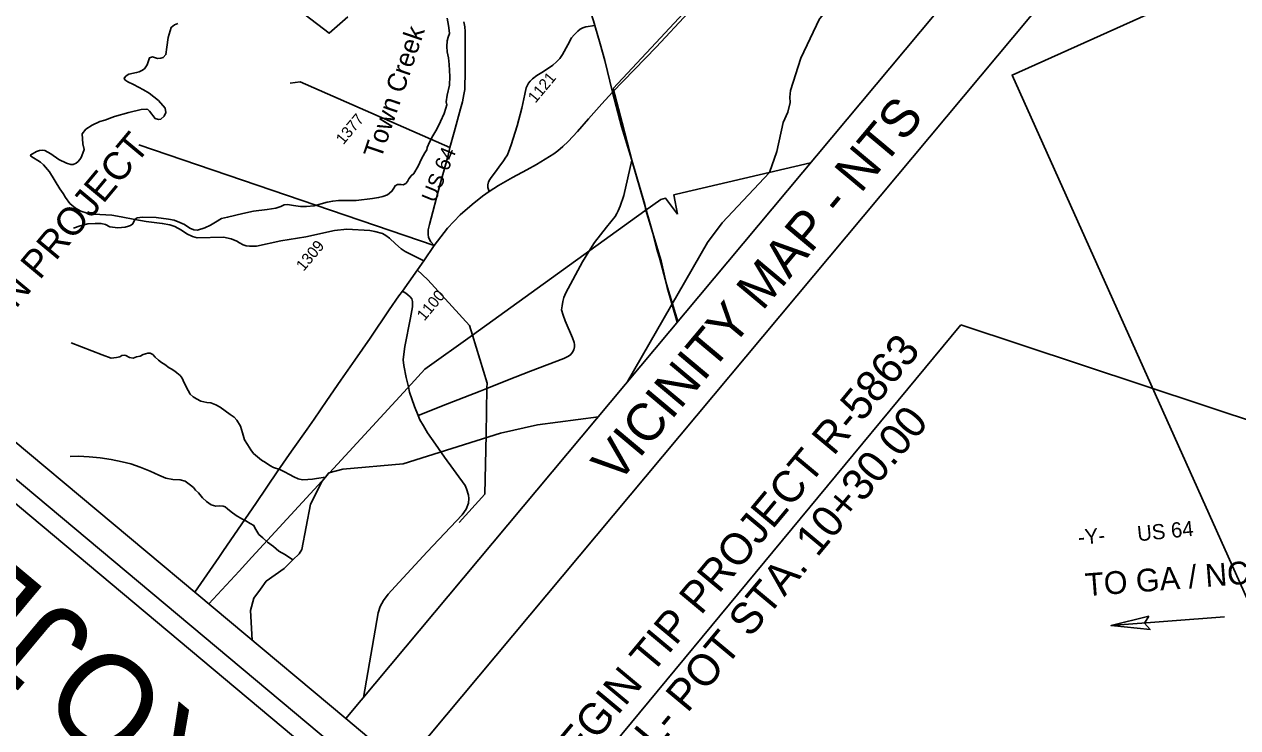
# Model space of a CAD drawing. Extents: x 555292 to 2368606, y 503623 to 1171444.
# Drawn here: x 2356645 to 2358242, y 1162339 to 1163265 of the extents above; entities that cross this region are included whole.
import ezdxf

# ---------------------------------------------------------------- set-up
doc = ezdxf.new("R2010")
doc.units = 0
for name, color, linetype in [('Exist Road Non-System Type 51 Label', 7, 'Continuous'), ('Exist Roads EOP Text', 7, 'Continuous'), ('Old_Level_1', 7, 'Continuous'), ('Old_Level_22', 7, 'Continuous'), ('Old_Level_28', 7, 'Continuous'), ('Old_Level_29', 7, 'Continuous'), ('Old_Level_3', 7, 'Continuous'), ('Old_Level_32', 7, 'Continuous'), ('Old_Level_48', 7, 'Continuous'), ('Old_Level_56', 7, 'Continuous'), ('Old_Level_59', 7, 'Continuous'), ('Old_Level_8', 7, 'Continuous'), ('Old_Level_9', 7, 'Continuous'), ('Prop DSN Text', 7, 'Continuous'), ('Prop Horizontal Alignment Station Label', 7, 'Continuous'), ('Prop Terminator CELL', 7, 'Continuous'), ('Sheet Title CELL', 7, 'Continuous')]:
    doc.layers.add(name, color=color, linetype=linetype)

msp = doc.modelspace()

# ---------------------------------------------------------------- linework, layer by layer
at = {"layer": 'Old_Level_1'}
for p, q in [((2357068.1, 1162351.5), (2358136.3, 1163628.5)), ((2357143.5, 1162288.4), (2358211.7, 1163565.5)), ((2356412.4, 1162899.9), (2357068.1, 1162351.5)), ((2357068.1, 1162351.5), (2357143.5, 1162288.4))]:
    msp.add_line(p, q, dxfattribs=at)
at = {"layer": 'Old_Level_28'}
for p, q in [((2357170.5, 1162954), (2357184.4, 1162973.8)), ((2357142.5, 1162913.7), (2357170.5, 1162954))]:
    msp.add_line(p, q, dxfattribs=at)
for points in [[(2357419.1, 1163175.7), (2357476.6, 1163235.1), (2357518.9, 1163280.7), (2357554.9, 1163318.7)], [(2357205, 1163102.7), (2357210.7, 1163123), (2357219.1, 1163153.8), (2357221.4, 1163162.8), (2357223.4, 1163172.6), (2357224.5, 1163179.4), (2357224.8, 1163184.8), (2357225.2, 1163198.3), (2357225, 1163217.1), (2357224.9, 1163249.2), (2357225.1, 1163255.4), (2357224.6, 1163261.8), (2357223.3, 1163268.1)], [(2357256.7, 1163045.1), (2357269.2, 1163052.8), (2357287.2, 1163063.4), (2357306.2, 1163073.6), (2357319.1, 1163080.6), (2357342, 1163094.4), (2357347, 1163098.5), (2357353.8, 1163104.4), (2357360.8, 1163111), (2357372.9, 1163123.9), (2357387.6, 1163140.8), (2357404.9, 1163160.3), (2357419.1, 1163175.7)], [(2357184.4, 1162973.8), (2357179.9, 1162979), (2357176.7, 1162984.6), (2357176.4, 1162988.9), (2357176.6, 1162994.6), (2357178, 1163001.8), (2357191.9, 1163053.2), (2357202.8, 1163092.4), (2357205, 1163102.7)], [(2357184.4, 1162973.8), (2357188.8, 1162979.8), (2357201.7, 1162996.6), (2357218.4, 1163014.5), (2357234.4, 1163028.1), (2357248, 1163038.9), (2357256.7, 1163045.1)], [(2357017, 1162732.3), (2357026.3, 1162745.6), (2357043.1, 1162770.2), (2357061.4, 1162796.7), (2357079.7, 1162823), (2357099.9, 1162852), (2357125.2, 1162889.5), (2357138, 1162907.8), (2357142.5, 1162913.7)], [(2356926.4, 1162600.6), (2356949.5, 1162634.3), (2356978.5, 1162677.3), (2356996.7, 1162703.3), (2357017, 1162732.3)], [(2356869.3, 1162517.7), (2356900.9, 1162563.6), (2356906, 1162571.4), (2356926.4, 1162600.6)]]:
    msp.add_lwpolyline(points, dxfattribs=at)
at = {"layer": 'Old_Level_29'}
for points in [[(2357395.7, 1163263.5), (2357394.2, 1163269.4), (2357387.6, 1163290)], [(2357419.1, 1163175.7), (2357409.1, 1163217.5), (2357402.9, 1163239.3), (2357395.7, 1163263.5)], [(2357444.3, 1163086.3), (2357431.1, 1163130.4), (2357419.1, 1163175.7)], [(2357504.2, 1162872.9), (2357491.2, 1162918.8), (2357482.9, 1162953.6), (2357479.8, 1162965.2), (2357472, 1162990.3), (2357463.1, 1163020.3), (2357461.7, 1163028), (2357444.3, 1163086.3)]]:
    msp.add_lwpolyline(points, dxfattribs=at)
at = {"layer": 'Old_Level_3'}
for p, q in [((2357419.7, 1163180.5), (2357475.9, 1163240.5)), ((2357419.7, 1163180.5), (2357419.7, 1163180.6)), ((2357431.8, 1163135.2), (2357419.7, 1163180.5)), ((2357445.1, 1163084.4), (2357431.8, 1163135.2))]:
    msp.add_line(p, q, dxfattribs=at)
for points in [[(2357475.9, 1163240.5), (2357518.3, 1163285.6), (2357553.3, 1163322.8), (2357570.3, 1163340.6)], [(2357480.9, 1162957.6), (2357477.9, 1162967.5), (2357471.1, 1162993.2), (2357460.4, 1163031.5), (2357445.1, 1163084.4)], [(2357505.1, 1162873.9), (2357490.3, 1162923), (2357480.9, 1162957.6)]]:
    msp.add_lwpolyline(points, dxfattribs=at)
at = {"layer": 'Old_Level_32'}
for points in [[(2356846.9, 1163265.9), (2356842.7, 1163264.4), (2356838.3, 1163260.8), (2356834.2, 1163247.5), (2356832.3, 1163234.8), (2356831.2, 1163225.2), (2356827.5, 1163221.4), (2356824.6, 1163220.4), (2356820.1, 1163220), (2356813.4, 1163222.1), (2356809.5, 1163220.8), (2356806.6, 1163211.5), (2356803, 1163206.3), (2356799.7, 1163204.4), (2356795.9, 1163202.5), (2356792.5, 1163201.4), (2356782.4, 1163199.6), (2356779.1, 1163197.4), (2356776.2, 1163194.2), (2356777, 1163192.1), (2356781.1, 1163189.4), (2356788.7, 1163185.7), (2356801.8, 1163178.7), (2356809, 1163174.2), (2356821.6, 1163164.6), (2356830.4, 1163154.8), (2356831.2, 1163149.1), (2356829, 1163144.2), (2356824.4, 1163140), (2356821.3, 1163139.8), (2356817, 1163141.1), (2356809.5, 1163150.7), (2356807.3, 1163152.9), (2356805, 1163153.2), (2356798.8, 1163152.9), (2356782.5, 1163148.9), (2356763.4, 1163143.6), (2356750.8, 1163139), (2356744.1, 1163137)], [(2357395.7, 1163263.5), (2357383.8, 1163261.7), (2357379.9, 1163260.2), (2357376.5, 1163258.4), (2357373.3, 1163256), (2357368.5, 1163251.3), (2357365.2, 1163247.2), (2357360.1, 1163238.1), (2357353.4, 1163225.3), (2357349.7, 1163219.9), (2357345.5, 1163215.4), (2357340.4, 1163211.2), (2357328.4, 1163203), (2357319.6, 1163197.5), (2357313.9, 1163193.4), (2357310.7, 1163190.3), (2357308.6, 1163187.4), (2357305.6, 1163181.4), (2357303.5, 1163173), (2357299.9, 1163154.7), (2357293.4, 1163131.2), (2357285.6, 1163106.2), (2357282.1, 1163096.6), (2357280.3, 1163092.5), (2357278.8, 1163090.1), (2357275.5, 1163085.2), (2357269.4, 1163077), (2357264.9, 1163070.9), (2357259.4, 1163063.4), (2357257.5, 1163061), (2357255.9, 1163057.6), (2357255, 1163053.9), (2357255, 1163050.1), (2357256.7, 1163045.1)], [(2357205, 1163102.7), (2357008.1, 1163189.4), (2356994.6, 1163187.4)], [(2356744.1, 1163137), (2356734, 1163132.2), (2356725.8, 1163126.9), (2356721.1, 1163120.8), (2356721.7, 1163107.6), (2356723.4, 1163100.4), (2356720.7, 1163092), (2356719.2, 1163088.7), (2356715.9, 1163084.7), (2356713.1, 1163082.4), (2356709.1, 1163080.7), (2356706.2, 1163080.6), (2356700.4, 1163082.2), (2356690.4, 1163087.2), (2356679.6, 1163094.7), (2356671.7, 1163099), (2356668.8, 1163099.4), (2356664.9, 1163098.9), (2356660.7, 1163097.7), (2356653.2, 1163093.3), (2356653, 1163092.5), (2356653.4, 1163091.6), (2356666, 1163083.6), (2356670, 1163079.9), (2356678, 1163070.7), (2356691.4, 1163048.6), (2356695.9, 1163042.5), (2356699, 1163037.2), (2356704.8, 1163029.3), (2356712.4, 1163023.2), (2356719.4, 1163019.3), (2356727.7, 1163016.7), (2356736.5, 1163015.3), (2356760, 1163014), (2356772.1, 1163011.9), (2356790.3, 1163008), (2356805.3, 1163005.7), (2356826.4, 1163003.1), (2356836.5, 1163001.2), (2356843, 1162998.9), (2356851.8, 1162994.1), (2356858.9, 1162989.1), (2356866, 1162985.7), (2356872.2, 1162984), (2356907, 1162984.8), (2356916.9, 1162982.7), (2356924.4, 1162979.7), (2356927.9, 1162977.3), (2356932.7, 1162974.9), (2356936.7, 1162973.7), (2356941.5, 1162972.9), (2356950.6, 1162973.2), (2356982.6, 1162980.3), (2357015.5, 1162985.5), (2357053.3, 1162993.6), (2357069.5, 1162995.3), (2357099.7, 1162993.5), (2357106.2, 1162992.6), (2357116.4, 1162989.6), (2357120.9, 1162987.2), (2357125.3, 1162983.8), (2357133.4, 1162976.1), (2357140.7, 1162969.5), (2357146.1, 1162966.1), (2357170.5, 1162954)], [(2357444.3, 1163086.3), (2357433.9, 1163039.8), (2357429.1, 1163025.7), (2357426.5, 1163019.6), (2357424.8, 1163016.1), (2357422.4, 1163012.1), (2357411, 1162998.2), (2357395.3, 1162978), (2357387.7, 1162966), (2357379.5, 1162952.6), (2357357.8, 1162911.9), (2357354.8, 1162905.6), (2357353.5, 1162900.3), (2357352.6, 1162894.6), (2357352.1, 1162889.4), (2357353.9, 1162882.5), (2357356.7, 1162875), (2357366.6, 1162852.5), (2357368.4, 1162846.5), (2357369.2, 1162843.5), (2357368.9, 1162840.5), (2357368.1, 1162836.9), (2357366.6, 1162833.7), (2357364, 1162830.6), (2357361.2, 1162828.4), (2357355.1, 1162825.5), (2357311.3, 1162808.5), (2357281, 1162796.7), (2357253.8, 1162785.8), (2357244.7, 1162782.5), (2357202, 1162765.6), (2357163.3, 1162750.3)], [(2357163.3, 1162750.3), (2357158.2, 1162762.3), (2357151.7, 1162781.2), (2357150.5, 1162788.1), (2357147.5, 1162800.4), (2357144.3, 1162816), (2357143.7, 1162823.6), (2357144.3, 1162831.2), (2357145.7, 1162840.9), (2357153, 1162878.8), (2357155.8, 1162893.4), (2357155.9, 1162900.3), (2357154.7, 1162903.7), (2357152.6, 1162906.3), (2357149.8, 1162909), (2357147, 1162911.1), (2357142.5, 1162913.7)], [(2357091.4, 1162379.3), (2357110.6, 1162490.8), (2357113.2, 1162498.9), (2357117.5, 1162507), (2357123.8, 1162515.3), (2357132.9, 1162525.4), (2357174.9, 1162570.7), (2357221, 1162619.8), (2357226.3, 1162627), (2357229.4, 1162635), (2357230.1, 1162641.1), (2357229.5, 1162645.6), (2357226.8, 1162653.9), (2357224.9, 1162658.3), (2357197.7, 1162695.5), (2357186.1, 1162712.5), (2357175.5, 1162727.4), (2357170.1, 1162736.9), (2357165.5, 1162744.8), (2357163.3, 1162750.3)]]:
    msp.add_lwpolyline(points, dxfattribs=at)
at = {"layer": 'Old_Level_48'}
msp.add_lwpolyline([(2357070.8, 1163274.7), (2357046, 1163253.3), (2356975.5, 1163307.8)], dxfattribs=at)
at = {"layer": 'Old_Level_56'}
for p, q in [((2357503.3, 1163041.5), (2357679.7, 1163082.7)), ((2357461.8, 1163019.4), (2357389.4, 1162967.3)), ((2357389.4, 1162967.3), (2357234.8, 1162856.2))]:
    msp.add_line(p, q, dxfattribs=at)
for points in [[(2357504.6, 1163015.4), (2357489, 1163036.1), (2357482.7, 1163034.5), (2357461.8, 1163019.4)], [(2357504.6, 1163015.4), (2357499.8, 1163040.7), (2357503.3, 1163041.5)], [(2357234.8, 1162856.2), (2357231, 1162868.8), (2357176, 1162928.6), (2357161.9, 1162942)], [(2357234.8, 1162856.2), (2357172.2, 1162811.1), (2357149.1, 1162786.1)], [(2357253.8, 1162786.5), (2357253.9, 1162792.9), (2357234.8, 1162856.2)], [(2357149.1, 1162786.1), (2356944.4, 1162563.8), (2356927.7, 1162545.6)], [(2357217.3, 1162609.7), (2357250.9, 1162646.7), (2357252.6, 1162725.5), (2357253.8, 1162786.5)], [(2356927.7, 1162545.6), (2356887.8, 1162502.3)]]:
    msp.add_lwpolyline(points, dxfattribs=at)
at = {"layer": 'Old_Level_59'}
for points in [[(2357438.4, 1162794.2), (2357544, 1162977.9), (2357563.6, 1163004), (2357625.7, 1163070.2), (2357635.3, 1163097.7), (2357643.8, 1163135.7), (2357649.7, 1163149.3), (2357653.1, 1163161.9), (2357652.5, 1163169), (2357653.3, 1163177.9), (2357666.9, 1163220.3), (2357691.4, 1163272.1), (2357721.1, 1163306), (2357729.9, 1163340.4), (2357732.6, 1163348.3), (2357736.3, 1163365.3), (2357745.6, 1163393.3), (2357750.1, 1163401.4)], [(2356709.4, 1162996.7), (2356718.3, 1162999.8), (2356728.4, 1163002.4), (2356738.3, 1163002.8), (2356745.9, 1163002.7), (2356751.5, 1163001.7), (2356757.3, 1162998.7), (2356768.1, 1162997.1), (2356777.5, 1162998.2), (2356782, 1162999.2), (2356784.8, 1163000.1), (2356787.5, 1163002.5), (2356789.5, 1163006.4), (2356790.7, 1163008.8), (2356793.5, 1163010.3), (2356800.5, 1163011.4), (2356818.4, 1163010.6), (2356834.5, 1163008.4), (2356841.9, 1163007.3), (2356849.7, 1163004.3), (2356855.8, 1163001.7), (2356862.8, 1162996.8), (2356868.1, 1162994.6), (2356872.9, 1162994.2), (2356882.3, 1162997.2), (2356889.8, 1163000.6), (2356896.6, 1163004.6), (2356904.2, 1163009.5), (2356912.3, 1163011.2), (2356932.4, 1163016), (2356946.4, 1163019.1), (2356964.4, 1163021.4), (2356976.1, 1163023.3), (2356982.4, 1163025.1), (2356986.7, 1163027.4), (2356991.1, 1163027.9), (2356999.1, 1163026.8), (2357008.2, 1163025.4), (2357016.2, 1163025.2), (2357026.2, 1163026.3), (2357035.5, 1163028.9), (2357043.3, 1163031.1), (2357050.8, 1163032.4), (2357058.3, 1163033), (2357081.8, 1163033.3), (2357103.2, 1163036), (2357111.2, 1163037), (2357116.8, 1163038.3), (2357122.8, 1163040.6), (2357128.6, 1163045.3), (2357131.2, 1163049.4), (2357132.8, 1163052.6), (2357136.2, 1163054.4), (2357140.8, 1163054.1), (2357143.7, 1163053.9), (2357146.9, 1163055.6), (2357149.2, 1163058.1), (2357151, 1163061.8), (2357153.9, 1163065.7), (2357157.6, 1163068.6), (2357163.4, 1163078.4), (2357167.8, 1163088), (2357172.1, 1163095.7), (2357174.5, 1163100), (2357175, 1163103.1), (2357178, 1163109.9), (2357182.4, 1163118.1), (2357187.8, 1163127.2), (2357192.5, 1163137.3), (2357197.4, 1163147.8), (2357199.8, 1163154.8), (2357201.1, 1163159.1), (2357200.2, 1163162.9), (2357201.5, 1163171.9), (2357204.5, 1163185.1), (2357204.8, 1163196.3), (2357204.2, 1163212.2), (2357203.3, 1163220.9), (2357201.6, 1163228.8), (2357201.1, 1163235.6), (2357201.2, 1163243.1), (2357202.8, 1163247.9), (2357204.4, 1163252.7), (2357204.1, 1163256.8), (2357203.3, 1163263.5), (2357201.4, 1163272.9)], [(2356706.6, 1162845.8), (2356747.5, 1162830.1), (2356759.1, 1162825.8), (2356766.1, 1162826.6), (2356770.4, 1162827.6), (2356773.3, 1162829.2), (2356776.1, 1162829.6), (2356778.5, 1162829.3), (2356783.1, 1162826.6), (2356788, 1162825.9), (2356792.4, 1162827.5), (2356797.3, 1162828.4), (2356801.4, 1162830.6), (2356804.3, 1162831.4), (2356807.3, 1162832.2), (2356810.5, 1162832.5), (2356813.8, 1162830.5), (2356817.2, 1162827.1), (2356821.3, 1162822.9), (2356825.2, 1162820.1), (2356829.6, 1162817.4), (2356835.5, 1162813.2), (2356838.3, 1162811.8), (2356842.8, 1162808.7), (2356845.7, 1162806.5), (2356849.9, 1162803.1), (2356852.5, 1162799.6), (2356853.7, 1162796.3), (2356857.1, 1162789.6), (2356860.7, 1162783.2), (2356863.2, 1162778.2), (2356867, 1162774.7), (2356871.3, 1162772), (2356877.1, 1162769.3), (2356884.9, 1162767.5), (2356890.3, 1162766.8), (2356896.9, 1162764.5), (2356902.8, 1162761.2), (2356909.2, 1162756.6), (2356915.6, 1162751.7), (2356921.2, 1162747.9), (2356924.4, 1162744.3), (2356929.4, 1162736.4), (2356932.1, 1162727.6), (2356934.7, 1162718.3), (2356938.5, 1162712.1), (2356942.8, 1162705), (2356946.5, 1162700.2), (2356951.7, 1162696), (2356956.9, 1162691.6), (2356962.3, 1162688.6), (2356968.1, 1162684.5), (2356972.7, 1162681.8), (2356981.3, 1162679.3), (2356987.2, 1162676.2), (2356994.1, 1162672.8), (2356999.7, 1162669.7), (2357005.2, 1162667.1), (2357010.8, 1162665.7), (2357018, 1162666.1), (2357024.1, 1162666.7), (2357029.5, 1162667.3), (2357041.1, 1162669.1)], [(2357400.4, 1162748.7), (2357320.3, 1162737.8), (2357271.8, 1162727), (2357143.3, 1162686.9), (2357063.9, 1162679.6), (2357045.8, 1162674.8), (2357041.1, 1162669.1)], [(2356705.3, 1162696.2), (2356716.2, 1162696.8), (2356730.2, 1162696), (2356744.7, 1162694.5), (2356759, 1162692.5), (2356773.5, 1162689.5), (2356785, 1162686.9), (2356797.4, 1162682.2), (2356810.7, 1162677.2), (2356821.9, 1162671.6), (2356831, 1162667.8), (2356840.2, 1162666.3), (2356849.9, 1162665.5), (2356856.6, 1162663.9), (2356863.6, 1162658.7), (2356867.7, 1162655.5), (2356870.3, 1162652.2)], [(2357041.1, 1162669.1), (2357036.8, 1162663.9), (2357021.7, 1162633.6), (2357009.9, 1162574.2), (2357006.5, 1162568.3), (2356998.2, 1162560.2)], [(2356870.3, 1162652.2), (2356874, 1162648.5), (2356879.2, 1162642), (2356884.6, 1162637.2), (2356890.6, 1162632.7), (2356896.7, 1162631.1), (2356902.1, 1162631.3), (2356906.5, 1162631), (2356909.4, 1162630), (2356912.4, 1162627.4), (2356917, 1162623.4), (2356923.7, 1162618.6), (2356931.3, 1162614.2), (2356936.6, 1162611.6), (2356942.3, 1162608.3), (2356946.9, 1162605.6), (2356948.2, 1162602.3), (2356950.7, 1162598), (2356953.4, 1162593.8), (2356958.7, 1162589.2), (2356964.8, 1162583.7), (2356972.8, 1162577.9), (2356979.9, 1162571.9), (2356988.4, 1162567), (2356998.2, 1162560.2)], [(2356998.2, 1162560.2), (2356986.8, 1162549.1), (2356963.3, 1162532.2), (2356955.6, 1162521.7)], [(2356955.6, 1162521.7), (2356946.9, 1162509.9), (2356942.4, 1162493.7), (2356944.7, 1162454.7)]]:
    msp.add_lwpolyline(points, dxfattribs=at)
at = {"layer": 'Prop DSN Text'}
for p, q in [((2357184.4, 1162973.8), (2356795.4, 1163106.3)), ((2358075.4, 1162473.8), (2358224.4, 1162485.2))]:
    msp.add_line(p, q, dxfattribs=at)
at = {"layer": 'Prop Horizontal Alignment Station Label'}
for p, q in [((2357877.6, 1162869.6), (2357370.7, 1162258.1)), ((2358485.2, 1162668), (2357877.6, 1162869.6))]:
    msp.add_line(p, q, dxfattribs=at)
at = {"layer": 'Prop Terminator CELL'}
msp.add_lwpolyline([(2358125, 1162486.3), (2358075.4, 1162473.8), (2358126.6, 1162468.7), (2358119.5, 1162477.2)], close=True, dxfattribs=at)
at = {"layer": 'Sheet Title CELL'}
for p, q in [((2359126.1, 1160581.9), (2355923.7, 1163260.5)), ((2359819.6, 1159969.2), (2355907.6, 1163241.3))]:
    msp.add_line(p, q, dxfattribs=at)
msp.add_lwpolyline([(2359897.4, 1162918.3), (2358377.2, 1162235.6), (2357945, 1163198.1), (2359465.2, 1163880.8)], close=True, dxfattribs=at)

# ---------------------------------------------------------------- texts
at = {"layer": 'Exist Road Non-System Type 51 Label'}
msp.add_text('Town Creek', height=25, rotation=71.2235, dxfattribs=at).set_placement((2357114.3, 1163086.8))
at = {"layer": 'Exist Roads EOP Text'}
for s, rotation, p in [('-Y-', 5.1942, (2358032.6, 1162579.9)), ('US 64', 5.6649, (2358110.7, 1162584.7))]:
    msp.add_text(s, height=20, rotation=rotation, dxfattribs=at).set_placement(p)
at = {"layer": 'Old_Level_22'}
msp.add_text('BEGIN PROJECT', height=36.575, rotation=50.2196, dxfattribs=at).set_placement((2356559, 1162800.2))
at = {"layer": 'Old_Level_8'}
for s, height, rotation, p in [('1121', 14.76, 50.0895, (2357317.6, 1163160.5)), ('VICINITY MAP - NTS', 49.341, 50.0896, (2357425.8, 1162659)), ('1377', 14.76, 50.0895, (2357064.8, 1163105.8)), ('1309', 14.76, 50.0895, (2357012.5, 1162939.3)), ('1100', 14.76, 50.0895, (2357171.4, 1162873.9))]:
    msp.add_text(s, height=height, rotation=rotation, dxfattribs=at).set_placement(p)
at = {"layer": 'Old_Level_9'}
msp.add_text('US 64', height=20, rotation=67.6639, dxfattribs=at).set_placement((2357185.4, 1163029.3))
at = {"layer": 'Prop DSN Text'}
msp.add_text('TO GA / NC STATE LINE', height=30, rotation=4.3797, dxfattribs=at).set_placement((2358042.4, 1162512.5))
at = {"layer": 'Prop Horizontal Alignment Station Label'}
for s, p in [('BEGIN TIP PROJECT R-5863', (2357350.9, 1162265.1)), ('-L- POT STA. 10+30.00', (2357464.7, 1162294.3))]:
    msp.add_text(s, height=41.248, rotation=50.1994, dxfattribs=at).set_placement(p)
at = {"layer": 'Sheet Title CELL'}
msp.add_text('PROJECT:', height=125, rotation=140.0895, dxfattribs=at).set_placement((2357020.1, 1162230.5))

doc.saveas('drawing.dxf')
